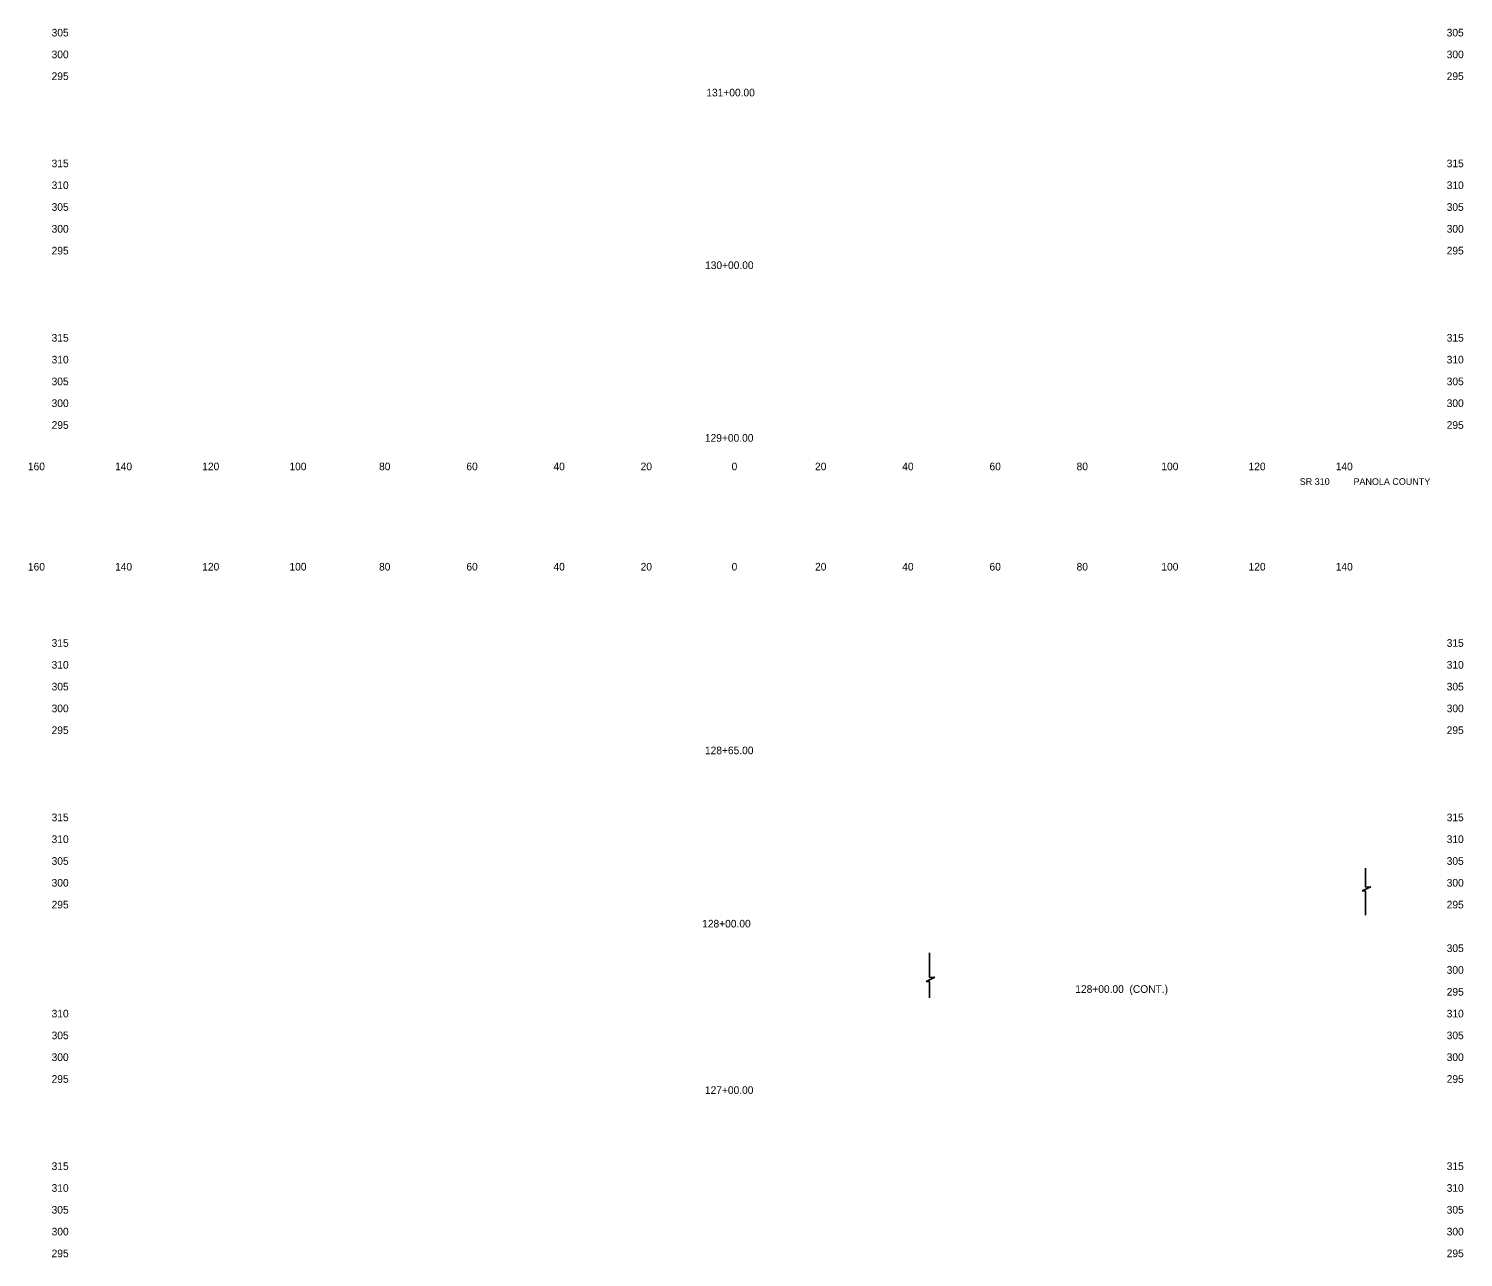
# Model space of a CAD drawing. Extents: x 21481 to 21810, y 6485 to 11067.
# Drawn here: x 21480.9 to 21809.9, y 9067.7 to 9349.5 of the extents above; entities that cross this region are included whole.
import ezdxf

# ---------------------------------------------------------------- set-up
doc = ezdxf.new("R2010")
doc.units = 0
for name, color, linetype in [('62', 7, 'Continuous'), ('XS_CELL', 7, 'Continuous'), ('XS_P_SUBGRADE_GRANULAR', 7, 'Continuous'), ('XS_P_TX_DCH', 7, 'Continuous'), ('XS_P_TX_FS_BS', 7, 'Continuous')]:
    doc.layers.add(name, color=color, linetype=linetype)

msp = doc.modelspace()

# ---------------------------------------------------------------- linework, layer by layer
at = {"layer": 'XS_P_SUBGRADE_GRANULAR'}
for p, q in [((21787.54, 9156.91), (21787.53, 9152.59)), ((21788.72, 9152.68), (21786.72, 9151.72)), ((21786.72, 9151.72), (21787.55, 9151.69)), ((21787.53, 9152.59), (21788.72, 9152.68)), ((21787.55, 9151.69), (21787.53, 9146.13)), ((21687.53, 9137.56), (21687.51, 9131.85)), ((21688.71, 9131.95), (21686.71, 9130.98)), ((21687.51, 9131.85), (21688.71, 9131.95)), ((21686.71, 9130.98), (21687.53, 9130.95)), ((21687.53, 9130.95), (21687.53, 9127.2))]:
    msp.add_line(p, q, dxfattribs=at)

# ---------------------------------------------------------------- texts
at = {"layer": '62'}
for s, p in [('  160  ', (21479.4, 9248.21)), ('  140  ', (21499.39, 9248.21)), ('  120  ', (21519.39, 9248.21)), ('  100  ', (21539.39, 9248.21)), ('  80  ', (21559.95, 9248.21)), ('  60  ', (21579.97, 9248.21)), ('  40  ', (21599.95, 9248.21)), ('  20  ', (21619.95, 9248.21)), ('  0  ', (21640.81, 9248.21)), ('  0  ', (21640.81, 9248.21)), ('  20  ', (21659.95, 9248.21)), ('  40  ', (21679.95, 9248.21)), ('  60  ', (21699.97, 9248.21)), ('  80  ', (21719.95, 9248.21)), ('  100  ', (21739.39, 9248.21)), ('  120  ', (21759.39, 9248.21)), ('  140  ', (21779.39, 9248.21)), ('  160  ', (21479.4, 9225.21)), ('  140  ', (21499.39, 9225.21)), ('  120  ', (21519.39, 9225.21)), ('  100  ', (21539.39, 9225.21)), ('  80  ', (21559.95, 9225.21)), ('  60  ', (21579.97, 9225.21)), ('  40  ', (21599.95, 9225.21)), ('  20  ', (21619.95, 9225.21)), ('  0  ', (21640.81, 9225.21)), ('  0  ', (21640.81, 9225.21)), ('  20  ', (21659.95, 9225.21)), ('  40  ', (21679.95, 9225.21)), ('  60  ', (21699.97, 9225.21)), ('  80  ', (21719.95, 9225.21)), ('  100  ', (21739.39, 9225.21)), ('  120  ', (21759.39, 9225.21)), ('  140  ', (21779.39, 9225.21))]:
    msp.add_text(s, height=1.75, dxfattribs=at).set_placement(p)
at = {"layer": 'XS_CELL'}
for s, p in [('  305  ', (21484.84, 9347.71)), ('  305  ', (21804.84, 9347.71)), ('  300  ', (21484.84, 9342.71)), ('  300  ', (21804.84, 9342.71)), ('  295  ', (21484.84, 9337.71)), ('  295  ', (21804.84, 9337.71)), ('  315  ', (21484.84, 9317.71)), ('  315  ', (21804.84, 9317.71)), ('  310  ', (21484.84, 9312.71)), ('  310  ', (21804.84, 9312.71)), ('  305  ', (21484.84, 9307.71)), ('  305  ', (21804.84, 9307.71)), ('  300  ', (21484.84, 9302.71)), ('  300  ', (21804.84, 9302.71)), ('  295  ', (21484.84, 9297.71)), ('  295  ', (21804.84, 9297.71)), ('  315  ', (21484.84, 9277.71)), ('  315  ', (21804.84, 9277.71)), ('  310  ', (21484.84, 9272.71)), ('  310  ', (21804.84, 9272.71)), ('  305  ', (21484.84, 9267.71)), ('  305  ', (21804.84, 9267.71)), ('  300  ', (21484.84, 9262.71)), ('  300  ', (21804.84, 9262.71)), ('  295  ', (21484.84, 9257.71)), ('  295  ', (21804.84, 9257.71)), ('  315  ', (21484.84, 9207.71)), ('  315  ', (21804.84, 9207.71)), ('  310  ', (21484.84, 9202.71)), ('  310  ', (21804.84, 9202.71)), ('  305  ', (21484.84, 9197.71)), ('  305  ', (21804.84, 9197.71)), ('  300  ', (21484.84, 9192.71)), ('  300  ', (21804.84, 9192.71)), ('  295  ', (21484.84, 9187.71)), ('  295  ', (21804.84, 9187.71)), ('  315  ', (21484.84, 9167.71)), ('  315  ', (21804.84, 9167.71)), ('  310  ', (21484.84, 9162.71)), ('  310  ', (21804.84, 9162.71)), ('  305  ', (21484.84, 9157.71)), ('  305  ', (21804.84, 9157.71)), ('  300  ', (21484.84, 9152.71)), ('  300  ', (21804.84, 9152.71)), ('  295  ', (21484.84, 9147.71)), ('  295  ', (21804.84, 9147.71)), ('  305  ', (21804.84, 9137.71)), ('  300  ', (21804.84, 9132.71)), ('  295  ', (21804.84, 9127.71)), ('  310  ', (21484.84, 9122.71)), ('  310  ', (21804.84, 9122.71)), ('  305  ', (21484.84, 9117.71)), ('  305  ', (21804.84, 9117.71)), ('  300  ', (21484.84, 9112.71)), ('  300  ', (21804.84, 9112.71)), ('  295  ', (21484.84, 9107.71)), ('  295  ', (21804.84, 9107.71)), ('  315  ', (21484.84, 9087.71)), ('  315  ', (21804.84, 9087.71)), ('  310  ', (21484.84, 9082.71)), ('  310  ', (21804.84, 9082.71)), ('  305  ', (21484.84, 9077.71)), ('  305  ', (21804.84, 9077.71)), ('  300  ', (21484.84, 9072.71)), ('  300  ', (21804.84, 9072.71)), ('  295  ', (21484.84, 9067.71)), ('  295  ', (21804.84, 9067.71))]:
    msp.add_text(s, height=1.75, dxfattribs=at).set_placement(p)
at = {"layer": 'XS_P_TX_DCH'}
for s, p in [('  131+00.00  ', (21635.01, 9333.96)), ('  130+00.00  ', (21634.72, 9294.36)), ('  129+00.00  ', (21634.69, 9254.76)), ('  128+65.00  ', (21634.7, 9183.08)), ('  128+00.00  ', (21634.06, 9143.34)), ('  128+00.00  (CONT.)', (21719.65, 9128.34)), ('  127+00.00  ', (21634.69, 9105.16))]:
    msp.add_text(s, height=1.75, dxfattribs=at).set_placement(p)
at = {"layer": 'XS_P_TX_FS_BS'}
for s, p in [('SR 310', (21772.43, 9244.84)), ('SR 310', (21772.43, 9244.84)), ('SR 310', (21772.43, 9244.84)), ('PANOLA COUNTY', (21784.75, 9244.84)), ('PANOLA COUNTY', (21784.75, 9244.84)), ('PANOLA COUNTY', (21784.75, 9244.84))]:
    msp.add_text(s, height=1.54, dxfattribs=at).set_placement(p)

doc.saveas('drawing.dxf')
